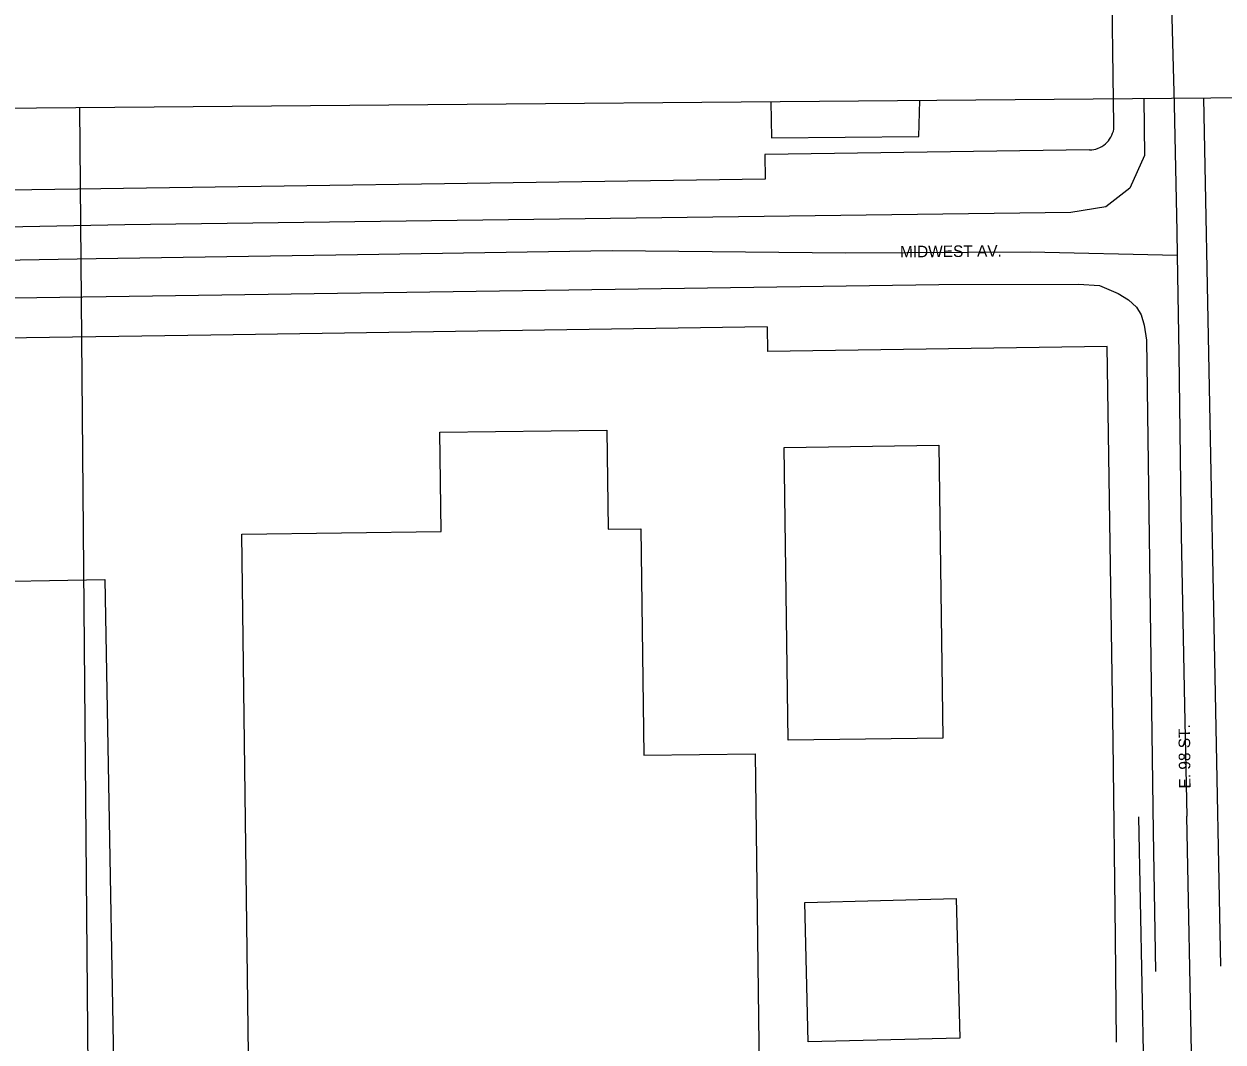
# Model space of a CAD drawing. Extents: x -2233 to 187241, y 4582 to 150524.
# Drawn here: x 106968.6 to 107455.5, y 59637.9 to 60051.5 of the extents above; entities that cross this region are included whole.
import ezdxf

# ---------------------------------------------------------------- set-up
doc = ezdxf.new("R2010")
doc.units = 0
for name, color, linetype in [('BLDG', 7, 'Continuous'), ('GE_X_CL_20', 7, 'Continuous'), ('GE_X_CL_2000', 7, 'Continuous'), ('GRID', 7, 'Continuous'), ('ROAD', 7, 'Continuous'), ('ROAD-NAME', 7, 'Continuous'), ('RW_X_Fee_RW', 7, 'Continuous')]:
    doc.layers.add(name, color=color, linetype=linetype)

msp = doc.modelspace()

# ---------------------------------------------------------------- linework, layer by layer
at = {"layer": 'BLDG'}
msp.add_lwpolyline([(107271.93, 60019.86), (107272.18, 60005.25), (107331.99, 60005.77), (107332.37, 60020.39)], dxfattribs=at)
for points in [[(107138.05, 59845.37), (107137.53, 59885.63), (107205.31, 59886.51), (107205.83, 59846.29), (107219.12, 59846.47), (107220.3, 59754.44), (107265.47, 59755.03), (107268.65, 59508.72), (107061.45, 59506.05), (107057.09, 59844.32)], [(107340.13, 59880.36), (107341.79, 59761.45), (107278.98, 59760.58), (107277.31, 59879.48)], [(107001.39, 59825.86), (107006.43, 59546.84), (106886.38, 59544.66), (106881.33, 59823.69)], [(107347.21, 59696.19), (107348.6, 59639.57), (107287.07, 59638.06), (107285.68, 59694.69)]]:
    msp.add_lwpolyline(points, close=True, dxfattribs=at)
at = {"layer": 'GE_X_CL_20'}
msp.add_line((107446.21, 59456.25), (107440.88, 59729.76), dxfattribs=at)
at = {"layer": 'GE_X_CL_2000'}
for points in [[(107398.88, 60610.72), (107399.47, 60591.2), (107401.13, 60556.19), (107402.1, 60543.58), (107404.07, 60524.82), (107406.57, 60505.93), (107420.75, 60421.1), (107423.69, 60401.77), (107426.36, 60382.4), (107427.91, 60366.28), (107429.21, 60350.14), (107430.39, 60331.55), (107431.07, 60317.8), (107431.64, 60301.62), (107431.96, 60285.42), (107432.03, 60269.23), (107433.19, 60187.36), (107433.83, 60089.56), (107435.73, 60018.68), (107436.7, 59967.15), (107436.88, 59957.54)], [(106912.75, 59954.74), (106997.92, 59956.22), (107104.03, 59957.9), (107207.45, 59959.46), (107302.16, 59958.53), (107377.23, 59959.01), (107436.88, 59957.54)], [(107436.88, 59957.54), (107437.62, 59917.41), (107438.5, 59843.81), (107439.82, 59774.67), (107440.88, 59729.76)]]:
    msp.add_lwpolyline(points, dxfattribs=at)
at = {"layer": 'GRID'}
for p, q in [((109991.08, 60043.59), (104991.27, 59999.96)), ((106991.2, 60017.41), (107014.74, 57319.74))]:
    msp.add_line(p, q, dxfattribs=at)
at = {"layer": 'ROAD'}
msp.add_line((107425.21, 59531.65), (107421.35, 59729.38), dxfattribs=at)
for points in [[(107423.33, 60021.19), (107423.65, 59998.08), (107417.66, 59984.78), (107407.98, 59977.21), (107393.75, 59974.88), (107009.56, 59969.91), (106843.87, 59966.62), (106816.89, 59967.09), (106795.19, 59972.34), (106776.45, 59979.65), (106759.48, 59990.01), (106746.6, 60002.59), (106734.66, 60016.42)], [(107454.67, 59668.7), (107447.69, 60021.4)], [(106860.98, 59938.82), (107340.13, 59945.68), (107396.84, 59945.75), (107405.38, 59945.21), (107412.94, 59942.04), (107417.17, 59939.48), (107420.32, 59936.48), (107422.31, 59933.39), (107423.51, 59929.21), (107424.38, 59923), (107427.13, 59723.38), (107428.12, 59666.61)]]:
    msp.add_lwpolyline(points, dxfattribs=at)
at = {"layer": 'RW_X_Fee_RW'}
for p, q in [((107401.34, 60000.38), (107269.39, 59998.45)), ((107269.39, 59998.45), (107269.53, 59988.45)), ((107270.42, 59928.45), (107270.57, 59918.45)), ((107408.51, 59920.48), (107270.57, 59918.45))]:
    msp.add_line(p, q, dxfattribs=at)
for points in [[(107411.19, 60010.53), (107410.16, 60080.52), (107409.57, 60120.52), (107408.99, 60160.51), (107408.4, 60200.51), (107407.81, 60240.5), (107407.23, 60280.5), (107406.85, 60306)], [(107401.34, 60000.38), (107402.21, 60000.41), (107403.07, 60000.48), (107403.92, 60000.59), (107404.75, 60001.04), (107405.55, 60001.38), (107406.32, 60001.79), (107407.05, 60002.27), (107407.73, 60002.82), (107408.36, 60003.41), (107408.94, 60004.07), (107409.46, 60004.77), (107409.92, 60005.51), (107410.31, 60006.29), (107410.64, 60007.1), (107411.06, 60007.94), (107411.14, 60008.79), (107411.18, 60009.66), (107411.19, 60010.53)], [(107269.53, 59988.45), (106953.14, 59983.8), (106858.15, 59982.41), (106831.15, 59982.01)], [(107270.42, 59928.45), (107044.49, 59925.14), (106838.61, 59922.11)], [(107410.86, 59760.5), (107409.68, 59840.49), (107408.51, 59920.48)], [(107412.31, 59637.84), (107411.81, 59680.5), (107410.86, 59760.5)]]:
    msp.add_lwpolyline(points, dxfattribs=at)

# ---------------------------------------------------------------- texts
at = {"layer": 'ROAD-NAME'}
for s, rotation, p in [('MIDWEST AV.', 0.5, (107324.34, 59956.66)), ('E. 98 ST.', 90.5, (107442.32, 59740.97))]:
    msp.add_text(s, height=4.68, rotation=rotation, dxfattribs=at).set_placement(p)

doc.saveas('drawing.dxf')
